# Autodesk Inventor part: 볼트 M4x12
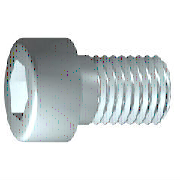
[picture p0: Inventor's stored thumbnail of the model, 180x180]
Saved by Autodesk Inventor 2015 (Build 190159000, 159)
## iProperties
IsCustomPart: 0
Created: 2012-02
Part Number: 볼트 M4x12
Material: 강철, 연강
Description: 6각 소켓 머리 캡 나사
Document SubType Name: Modeling
Standard: ISO 4762
Designer: mduedu
Standard Revision: Fourth edition 2004-03-01
Standards Organization: ISO
Language: ko-KR
Size Designation: M4 x 12
Categories: <MemberInstance><Categories><Category DisplayName="조임쇠" InternalName="e4da775c-781d-43d5-af7c-5136215cf5a6" Mnemonic="FSTN"><Category DisplayName="볼트" InternalN
Density: 7.75 g/cm^3
Appearance: 강철
Author: mduedu
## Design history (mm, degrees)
sketch "스케치1"
  geometry: L1 (-1, 0)-(12, 0); L2 (12, 0)-(12, 2); L3 (12, 2)-(1.75, 2); L4 (1.75, 2)-(1.32, 2); L5 (1.32, 2)-(0, 2); L6 (0, 2)-(0, 3.5); L7 (0, 3.5)-(-4, 3.5); L8 (-4, 3.5)-(-4, 1.732); L9 (-4, 1.732)-(-2, 1.732); L10 (-2, 1.732)-(-1, 0); L11 (-7.2, 0)-(15.2, 0) reference; L12 (0, -0.7)-(0, 4.2) reference; L13 (1.75, 2)-(0, 2)
  constraints: 22 end point, 6 parallel, 2 collinear, 2 perpendicular, 1 horizontal, 1 point on line
  dimensions: "d1" = 10.25 distance from line of L3.end L2 (= GEL); "d2" = 0.42952 distance of L4.end L3.end (computed from GAL); "d3" = 4 distance between parallel lines of L8 L6 (= KOH); "d4" = 2 distance of L8.end L9.end (= INTI); "d5" = 60 deg angle of L10 L1; "d6" = 4 diameter of L3 L1 (= GD); "d7" = 4 diameter of L5 L1 (= BDM); "d8" = 3.4641 diameter of L9 L1 (= 1.1547 x SW); "d9" = 7 diameter of L7 L1 (= KOD); "d26" = 12 distance between parallel lines of L12 L2 (= NLG)
revolve "본체" sketch "스케치1" stored, may be unused: angle "d10" = 90 deg
sketch "스케치2"
  geometry: L1 (0, -4.9)-(0, 4.9) reference; L2 (-4.9, 0)-(4.9, 0) reference; L3 (1.732, 0)-(0.866, -1.5); L4 (0.866, -1.5)-(-0.866, -1.5); L5 (-0.866, -1.5)-(-1.732, 0); L6 (-1.732, 0)-(-0.866, 1.5); L7 (-0.866, 1.5)-(0.866, 1.5); L8 (0.866, 1.5)-(1.732, 0); 2 further points
  constraints: 12 end point, 1 coincident, 1 horizontal alignment, 1 point on line, 12 other
extrude "슬롯" join sketch "스케치2" stored distance "d11" = 10; taper "d12" = 0 deg
workplane "Work Plane1"
fillet "Fillet2" dims "d30" = 0.1 (= R)
body "Solid1"
fillet "모깎기1" dims "d17" = 0.4 (= RR)
feature "스레드" dims "d13" = 10.25 (= GEL), "d14" = 0
chamfer "모따기1" distance "d15" = 0.42941 (= -0.5 x SPD + 0.5 x GD); stored, may be unused: second distance "d16" = 0.42941 (= GUL), angle "d27" = 45 deg
other parameters: "GD" = 4 [user parameter; used in 2 equation terms], "NLG" = 12 [user parameter; used in 1 equation term], "GEL" = 10.25 [user parameter; used in 2 equation terms], "KOD" = 7 [user parameter; used in 1 equation term], "KOH" = 4 [user parameter; used in 1 equation term], "INTI" = 2 [user parameter; used in 1 equation term], "GAL" = 0.42941 (= 0.61345 x PTC) [user parameter; used in 1 equation term], "GUL" = 0.42941 (= 0.61345 x PTC) [user parameter; used in 1 equation term], "BDM" = 4 (= NND) [user parameter; used in 1 equation term], "SW" = 3 [user parameter; used in 2 equation terms], "RR" = 0.4 [user parameter; used in 1 equation term], "SPD" = 3.14117 (= NND - 1.2269 x PTC) [user parameter; used in 1 equation term], "d19" = 0, "d28" = 0, "d29" = 0, "R" = 0.1 [user parameter; used in 1 equation term], "TOA" = 30 deg [user parameter], "GD1" = 3.14117 (= THREADDIA - 1.2269 x PTC) [user parameter], "THREADDIA" = 4 [user parameter; used in 1 equation term], "FAWI" = 45 deg [user parameter], "TPU" = 14.28571 (computed from PTC) [user parameter], "PTC" = 0.7 [user parameter; used in 5 equation terms], "NND" = 4 [user parameter; used in 2 equation terms], "E0" = 3.465 (= 1.155 x SW) [user parameter]
